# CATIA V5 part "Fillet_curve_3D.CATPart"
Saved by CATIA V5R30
Part number: Part1
Bounding box of the stored display mesh (mm): x -53.144 to 62.813, y -26.849 to 28.582, z -46.959 to 56.805
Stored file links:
  D:\PROJECTS\CATIA V56R 2020\Resources\Parts File\c17_catia_v6_6r2020_prt\Fillet_curve_3D.CATPart
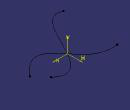
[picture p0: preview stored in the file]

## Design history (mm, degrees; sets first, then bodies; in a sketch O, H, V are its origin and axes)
Body1 (main body)
  Sketch1 on xy-plane, origin (0, 0, 0), H (1, 0, 0), V (0, 1, 0)
    spline S1 through (-53.144, 27.9693) (-18.6897, 19.5729) (20.5127, -19.6499) (62.8125, 1.293)
    coincidence: O S1
  Sketch2 on yz-plane, origin (0, 0, 0), H (0, 1, 0), V (0, 0, 1)
    spline S1 through (-6.7941, 56.8054) (-23.6522, 28.3211) (0, 0) (-26.8494, -46.959)
    point P1 (0, 0)
    coincidence: P1 H, P1 O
